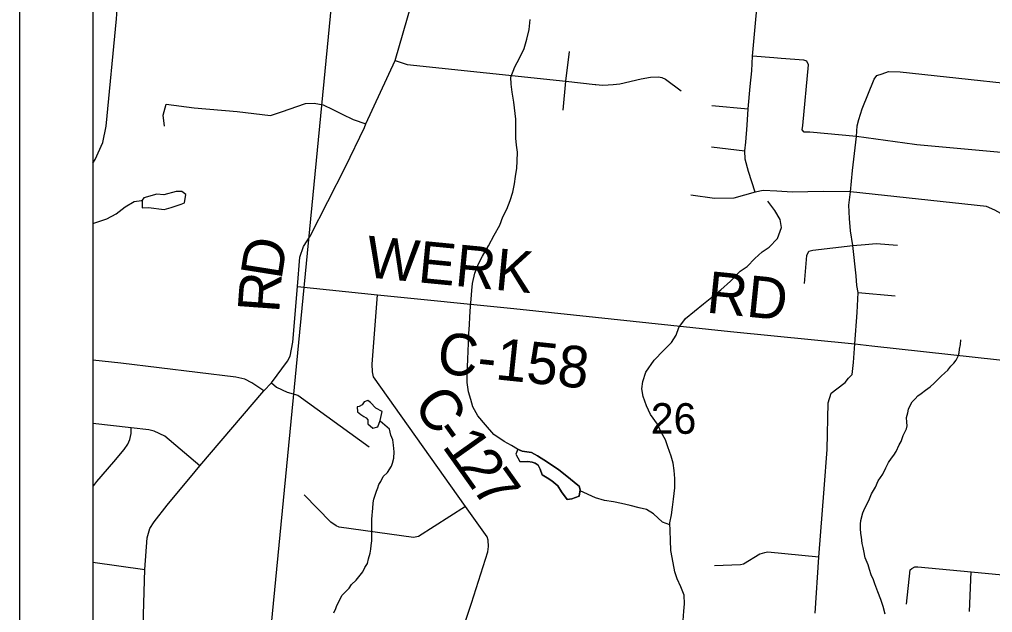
# Model space of a CAD drawing. Extents: x 0 to 34, y -2 to 22.
# Drawn here: x 2 to 3.329, y 19.146 to 19.956 of the extents above; entities that cross this region are included whole.
import ezdxf

# ---------------------------------------------------------------- set-up
doc = ezdxf.new("R2010")
doc.units = 0
for name, color, linetype in [('Default', 7, 'Continuous'), ('GM_X_County_Road', 7, 'Continuous'), ('GM_X_County_Road_Text', 7, 'Continuous'), ('GM_X_Minor_Lake', 7, 'Continuous'), ('GM_X_Minor_River', 7, 'Continuous'), ('GM_X_Rail_Line', 7, 'Continuous'), ('GM_X_Section', 7, 'Continuous'), ('GM_X_Section_Text', 7, 'Continuous'), ('GM_X_Township_Road', 7, 'Continuous'), ('SH_Cut_Line', 7, 'Continuous'), ('SH_Data', 7, 'Continuous')]:
    doc.layers.add(name, color=color, linetype=linetype)

msp = doc.modelspace()

# ---------------------------------------------------------------- linework, layer by layer
at = {"layer": 'Default'}
msp.add_lwpolyline([(2.1, 20.1369), (2.1, 19.1108), (2.3398, 19.083), (2.4387, 20.1012)], close=True, dxfattribs=at)
at = {"layer": 'GM_X_County_Road'}
msp.add_line((2.1, 19.2142), (2.1712, 19.2042), dxfattribs=at)
for points in [[(2.3338, 19.4483), (2.3443, 19.4595), (2.3661, 19.4889), (2.3697, 19.4957), (2.3732, 19.515), (2.3798, 19.5908), (2.3832, 19.631), (2.3882, 19.6456), (2.3969, 19.6595), (2.4454, 19.7543), (2.4712, 19.808), (2.4732, 19.813), (2.5131, 19.8995), (2.5409, 19.9962), (2.5554, 20.0405), (2.5666, 20.106), (2.5737, 20.177), (2.5781, 20.1967)], [(2.3798, 19.5908), (2.4889, 19.5795), (2.6752, 19.5607), (2.9711, 19.5296), (3.1409, 19.5124), (3.1645, 19.51), (3.4093, 19.4828)], [(2.5867, 19.0654), (2.6175, 19.1582), (2.6397, 19.2287), (2.6406, 19.2359), (2.6402, 19.2445), (2.6387, 19.2488), (2.6092, 19.2902), (2.4834, 19.4674), (2.4821, 19.4742), (2.4817, 19.4849), (2.4889, 19.5795)], [(2.2401, 19.3382), (2.2464, 19.3458), (2.3338, 19.4483)], [(2.1712, 19.2042), (2.1743, 19.2478), (2.178, 19.2602), (2.184, 19.2696), (2.2017, 19.2923), (2.2401, 19.3382)], [(2.1, 19.0714), (2.1174, 19.092), (2.1244, 19.0986), (2.1286, 19.1004), (2.1496, 19.1047), (2.1589, 19.1093), (2.1604, 19.11), (2.1668, 19.1189), (2.1689, 19.1276), (2.1712, 19.2042)]]:
    msp.add_lwpolyline(points, dxfattribs=at)
at = {"layer": 'GM_X_Minor_Lake'}
for points in [[(2.1977, 19.6963), (2.2072, 19.6987), (2.221, 19.7033), (2.2256, 19.7054), (2.2271, 19.7168), (2.2219, 19.7207), (2.2139, 19.7209), (2.1974, 19.7161), (2.1876, 19.7171), (2.17, 19.7122), (2.1676, 19.7087)], [(2.1676, 19.7087), (2.1677, 19.6982), (2.1761, 19.6988), (2.1977, 19.6963)], [(2.4926, 19.408), (2.4955, 19.4201), (2.4869, 19.4249), (2.4794, 19.4323), (2.4757, 19.4351), (2.4707, 19.4333), (2.468, 19.4292), (2.4641, 19.427), (2.4611, 19.4267), (2.4616, 19.4198), (2.4665, 19.4163), (2.4702, 19.4132), (2.4736, 19.4115), (2.4758, 19.4088)], [(2.4758, 19.4088), (2.476, 19.4031), (2.4827, 19.3976), (2.4896, 19.3993), (2.4926, 19.408)], [(2.6807, 19.3689), (2.6782, 19.3617), (2.6836, 19.352), (2.6943, 19.3521)], [(2.6805, 19.3689), (2.6867, 19.366), (2.6992, 19.3642), (2.7074, 19.3594), (2.7212, 19.351), (2.7369, 19.3403), (2.7499, 19.3301), (2.7604, 19.3215), (2.7644, 19.318), (2.7658, 19.313), (2.7645, 19.3046), (2.7545, 19.3011), (2.748, 19.3001), (2.7403, 19.3106), (2.7352, 19.3187), (2.727, 19.3254), (2.7207, 19.3294), (2.7139, 19.3337), (2.7111, 19.3414), (2.7086, 19.3468), (2.7045, 19.3496), (2.7003, 19.3508), (2.6943, 19.3521)], [(2.6943, 19.3521), (2.7003, 19.3508), (2.7045, 19.3496), (2.7086, 19.3468), (2.7111, 19.3414), (2.7139, 19.3337), (2.7207, 19.3294), (2.727, 19.3254), (2.7352, 19.3187), (2.7403, 19.3106), (2.748, 19.3001), (2.7545, 19.3011), (2.7645, 19.3046), (2.7658, 19.313), (2.7644, 19.318), (2.7604, 19.3215), (2.7499, 19.3301), (2.7369, 19.3403), (2.7212, 19.351), (2.7074, 19.3594), (2.6992, 19.3642), (2.6867, 19.366), (2.6807, 19.3689)]]:
    msp.add_lwpolyline(points, dxfattribs=at)
at = {"layer": 'GM_X_Minor_River'}
for points in [[(2.6805, 19.3689), (2.6722, 19.3736), (2.6621, 19.3792), (2.6479, 19.3887), (2.6365, 19.4019), (2.6263, 19.4144), (2.6194, 19.4264), (2.6166, 19.4364), (2.6135, 19.4471), (2.6116, 19.4597), (2.6115, 19.4703), (2.6122, 19.4813), (2.6125, 19.4916), (2.6129, 19.5026), (2.6132, 19.5136), (2.6139, 19.5269), (2.6147, 19.5387), (2.6154, 19.5497), (2.6161, 19.5634), (2.6168, 19.5736), (2.6179, 19.5854), (2.619, 19.5952), (2.622, 19.6092), (2.6269, 19.622), (2.6326, 19.6325), (2.6409, 19.6463), (2.6486, 19.6609), (2.6562, 19.6747), (2.6603, 19.686), (2.6656, 19.6965), (2.6701, 19.7082), (2.6738, 19.7199), (2.6761, 19.7312), (2.6775, 19.7414), (2.6793, 19.7524), (2.68, 19.7623), (2.6803, 19.7744), (2.6791, 19.784), (2.6782, 19.7935), (2.6782, 19.8068), (2.6782, 19.8197), (2.6751, 19.8426), (2.6732, 19.8564), (2.6716, 19.8671), (2.6712, 19.877), (2.6765, 19.8909), (2.6829, 19.9029), (2.6894, 19.916), (2.6932, 19.9288), (2.6962, 19.942), (2.6977, 19.9557)], [(2.1, 19.6768), (2.1194, 19.6832), (2.1321, 19.6901), (2.1446, 19.6996), (2.1569, 19.7069), (2.1665, 19.7085), (2.1676, 19.7087)], [(2.9064, 19.1346), (2.9076, 19.1475), (2.9086, 19.1573), (2.9078, 19.1691), (2.9036, 19.1806), (2.8986, 19.1914), (2.8954, 19.201), (2.8915, 19.2209), (2.8898, 19.2305), (2.8891, 19.2442), (2.8887, 19.2571), (2.8883, 19.2681), (2.8905, 19.2791), (2.8919, 19.2893), (2.8934, 19.3003), (2.895, 19.3159), (2.895, 19.3288), (2.8945, 19.3394), (2.8929, 19.3494), (2.8901, 19.359), (2.8856, 19.372), (2.8824, 19.3816), (2.8767, 19.392), (2.8713, 19.4028), (2.8618, 19.416), (2.8564, 19.428), (2.8519, 19.4407), (2.8503, 19.451), (2.8513, 19.4612), (2.8555, 19.474), (2.867, 19.4904), (2.8799, 19.5034), (2.8908, 19.5144), (2.8968, 19.5245), (2.9005, 19.5347), (2.91, 19.5474), (2.9221, 19.5573), (2.9345, 19.5672), (2.9458, 19.5764), (2.9582, 19.5863), (2.9711, 19.5981), (2.9844, 19.6118), (2.9941, 19.6183), (3.0047, 19.6291), (3.0144, 19.6383), (3.0241, 19.6448), (3.0355, 19.6567), (3.0408, 19.6714), (3.0393, 19.6824), (3.032, 19.6948), (3.0221, 19.7076)], [(3.1592, 19.2107), (3.1554, 19.2203), (3.1534, 19.2299), (3.1525, 19.2345), (3.1511, 19.2399), (3.1503, 19.2486), (3.1493, 19.2536), (3.1488, 19.2605), (3.1486, 19.2662), (3.1492, 19.2711), (3.1522, 19.2816), (3.1547, 19.288), (3.16, 19.2988), (3.1637, 19.3078), (3.1694, 19.3168), (3.1731, 19.3254), (3.1795, 19.3347), (3.1832, 19.3433), (3.1872, 19.3504), (3.1912, 19.3563), (3.1944, 19.3607), (3.1976, 19.3656), (3.2017, 19.3746), (3.2045, 19.379), (3.2071, 19.3873), (3.2095, 19.3918), (3.2116, 19.3966), (3.2125, 19.4008), (3.2119, 19.4058), (3.2117, 19.4118), (3.2135, 19.4182), (3.2144, 19.4235), (3.2165, 19.4284), (3.2193, 19.4332), (3.2236, 19.4373), (3.2272, 19.4417), (3.2319, 19.4446), (3.2377, 19.4493), (3.2439, 19.4537), (3.2494, 19.4588), (3.2545, 19.464), (3.2589, 19.4684), (3.264, 19.4728), (3.2679, 19.4768), (3.2723, 19.482), (3.2762, 19.486), (3.2794, 19.4905), (3.2822, 19.4957), (3.2835, 19.5002), (3.2841, 19.5055), (3.2854, 19.5119), (3.286, 19.518)], [(2.4691, 19.2011), (2.4719, 19.2071), (2.4752, 19.2127), (2.4769, 19.2187), (2.479, 19.2266), (2.48, 19.2319), (2.4806, 19.2372), (2.4812, 19.2437), (2.4813, 19.249), (2.4811, 19.2536), (2.4814, 19.2611), (2.4812, 19.268), (2.4814, 19.2733), (2.482, 19.2782), (2.4822, 19.2835), (2.4827, 19.2877), (2.4833, 19.2953), (2.4842, 19.3002), (2.4877, 19.3115), (2.4897, 19.316), (2.491, 19.3205), (2.4934, 19.3246), (2.4967, 19.3313), (2.5026, 19.3368), (2.5082, 19.3454), (2.5095, 19.3495), (2.5112, 19.3563), (2.5119, 19.365), (2.5111, 19.3741), (2.5102, 19.3814), (2.5074, 19.388), (2.5054, 19.396), (2.4929, 19.4071), (2.4926, 19.408)], [(2.8884, 19.2655), (2.8784, 19.2688), (2.8662, 19.2806), (2.8565, 19.2862), (2.8463, 19.2887), (2.8343, 19.2917), (2.8222, 19.2944), (2.8116, 19.2966), (2.7991, 19.2988), (2.7867, 19.3022), (2.7657, 19.312)], [(3.1827, 19.1434), (3.1797, 19.1537), (3.1783, 19.1579), (3.1766, 19.1633), (3.1724, 19.1737), (3.1686, 19.1849), (3.1665, 19.1903), (3.1633, 19.1972), (3.1613, 19.2045), (3.1592, 19.2107)], [(2.4292, 19.1451), (2.432, 19.1511), (2.4333, 19.1552), (2.441, 19.1694), (2.4504, 19.179), (2.4537, 19.1838), (2.4599, 19.19), (2.4635, 19.1945), (2.4691, 19.2011)]]:
    msp.add_lwpolyline(points, dxfattribs=at)
at = {"layer": 'GM_X_Rail_Line'}
msp.add_lwpolyline([(7.5809, 20.9), (2.1, 20.9), (2.1, 18.1368), (2.3446, 18.1102), (2.9298, 18.0171), (3.2869, 17.9604), (3.6832, 17.9108)], dxfattribs=at)
at = {"layer": 'GM_X_Section'}
msp.add_lwpolyline([(3.4541, 19.9967), (3.3818, 18.9832), (2.3398, 19.083), (2.4387, 20.1012)], close=True, dxfattribs=at)
at = {"layer": 'GM_X_Township_Road'}
for p, q in [((3.0306, 19.9031), (3.0015, 19.9057)), ((2.9459, 19.8381), (2.9953, 19.8335)), ((2.9453, 19.7817), (2.9906, 19.7763)), ((3.1454, 19.5828), (3.196, 19.5782)), ((3.2975, 19.1472), (3.3001, 19.201))]:
    msp.add_line(p, q, dxfattribs=at)
for points in [[(2.1, 19.7592), (2.1033, 19.7645), (2.114, 19.7875), (2.1183, 19.8101), (2.1325, 19.9567), (2.1345, 19.982), (2.1433, 20.0729)], [(2.9982, 19.8642), (3.0002, 19.8856), (3.0015, 19.9057), (3.0062, 19.9605), (3.0101, 19.9946), (3.0092, 20.0115), (3.008, 20.0229), (3.0037, 20.0394)], [(2.7427, 19.8318), (2.7462, 19.8716), (2.7512, 19.9119)], [(2.5131, 19.8995), (2.5298, 19.894), (2.7462, 19.8716), (2.7865, 19.8669), (2.7875, 19.8668)], [(3.2226, 19.785), (3.1435, 19.7956), (3.0796, 19.8017), (3.0719, 19.8017), (3.0693, 19.8049), (3.0702, 19.8107), (3.0776, 19.8935), (3.0756, 19.8985), (3.0716, 19.9002), (3.0403, 19.9022), (3.0306, 19.9031)], [(3.1435, 19.7956), (3.1444, 19.8106), (3.1465, 19.819), (3.1513, 19.8337), (3.1673, 19.8742), (3.1713, 19.879), (3.1782, 19.8815), (3.187, 19.8846), (3.2029, 19.8841), (3.4391, 19.8586)], [(2.7875, 19.8668), (2.7962, 19.8659), (2.8042, 19.8662), (2.8109, 19.8667), (2.8199, 19.8679), (2.8492, 19.8744), (2.8621, 19.8767), (2.8728, 19.8775), (2.8774, 19.8764), (2.8826, 19.8742), (2.9038, 19.8581)], [(3.005, 19.7196), (2.9957, 19.7478), (2.9915, 19.7649), (2.9906, 19.7763), (2.9921, 19.7883), (2.9942, 19.8115), (2.9953, 19.8335), (2.9982, 19.8642)], [(2.198, 19.8099), (2.1965, 19.825), (2.2002, 19.84), (2.2385, 19.8349), (2.2973, 19.8299), (2.3429, 19.8245), (2.3579, 19.8295), (2.3908, 19.8409), (2.4026, 19.8413), (2.4149, 19.839), (2.4281, 19.8327), (2.4406, 19.8261), (2.4559, 19.819), (2.4732, 19.813)], [(3.0868, 19.1448), (3.092, 19.221), (3.0993, 19.3146), (3.1031, 19.3681), (3.1048, 19.4322), (3.1086, 19.445), (3.1164, 19.4512), (3.128, 19.4596), (3.1324, 19.4659), (3.1376, 19.4708), (3.1391, 19.4873), (3.1409, 19.5124), (3.1442, 19.5552), (3.1454, 19.5828), (3.1439, 19.5924), (3.1427, 19.6053), (3.1382, 19.6468), (3.1353, 19.6669), (3.1338, 19.6839), (3.1329, 19.7019), (3.135, 19.7202), (3.138, 19.7496), (3.1435, 19.7956)], [(3.4345, 19.795), (3.4186, 19.7959), (3.4105, 19.7953), (3.4024, 19.792), (3.3924, 19.7847), (3.3807, 19.7753), (3.3706, 19.7724), (3.3612, 19.7723), (3.2256, 19.7846), (3.2226, 19.785)], [(3.0347, 19.721), (3.0158, 19.722), (3.005, 19.7196), (2.9756, 19.7115), (2.9495, 19.7112), (2.9172, 19.7155)], [(3.4238, 19.6478), (3.3826, 19.6512), (3.3762, 19.6529), (3.3445, 19.6885), (3.3325, 19.6954), (3.3211, 19.7002), (3.135, 19.7202), (3.0982, 19.7207), (3.0555, 19.7199), (3.0347, 19.721)], [(3.0723, 19.5951), (3.0757, 19.6333), (3.0783, 19.6393), (3.0836, 19.6406), (3.1382, 19.6468), (3.1553, 19.6483), (3.1702, 19.6498), (3.1993, 19.6472)], [(2.3338, 19.4483), (2.3172, 19.4594), (2.3077, 19.4644), (2.2956, 19.4671), (2.1385, 19.4861), (2.1, 19.4905)], [(2.3443, 19.4595), (2.3512, 19.4534), (2.3658, 19.4467), (2.3801, 19.4426), (2.4776, 19.3718)], [(2.2464, 19.3458), (2.1987, 19.3866), (2.1842, 19.3934), (2.1766, 19.3953), (2.1524, 19.3978), (2.1, 19.4038)], [(2.1, 19.3178), (2.1017, 19.3192), (2.1058, 19.3245), (2.1289, 19.3516), (2.143, 19.3682), (2.1481, 19.3757), (2.1506, 19.3818), (2.1525, 19.3902), (2.1524, 19.3978)], [(2.6092, 19.2902), (2.5449, 19.2496), (2.5384, 19.2479), (2.4368, 19.2622), (2.4327, 19.2639), (2.4253, 19.269), (2.389, 19.3063)], [(3.092, 19.221), (3.0222, 19.2278), (3.0177, 19.2272), (3.0115, 19.2251), (2.9891, 19.2118), (2.9849, 19.2108), (2.9492, 19.2093)], [(3.2117, 19.1568), (3.2167, 19.2041), (3.219, 19.2059), (3.2229, 19.2081), (3.226, 19.208), (3.2271, 19.2079), (3.3001, 19.201), (3.3907, 19.1924)]]:
    msp.add_lwpolyline(points, dxfattribs=at)
at = {"layer": 'SH_Cut_Line'}
msp.add_lwpolyline([(8.9, 20.9), (2.1, 20.9), (2.1, 16.3648), (2.1342, 16.3571), (2.2291, 16.3515), (2.5217, 16.3621), (2.6166, 16.3275), (2.9069, 16.2111), (3.202, 16.0321), (3.297, 15.9555), (3.6339, 15.5717)], dxfattribs=at)
at = {"layer": 'SH_Data'}
for p, q in [((2, 21), (2, 14)), ((2.1, 20.9), (2.1, 14.1))]:
    msp.add_line(p, q, dxfattribs=at)

# ---------------------------------------------------------------- texts
at = {"layer": 'GM_X_County_Road_Text'}
for s, height, rotation, p in [('WERK', 0.05682, 354.4546, (2.4717, 19.6038)), ('D', 0.0568, 80.9539, (2.3578, 19.5991)), ('R', 0.0568, 85.8454, (2.3546, 19.5539)), ('RD', 0.05682, 354.1938, (2.9371, 19.5555)), ('C-158', 0.05682, 353.9906, (2.5691, 19.4727)), ('C', 0.0568, 305.3822, (2.5362, 19.4293)), ('1', 0.0568, 305.3825, (2.5764, 19.3727)), ('-', 0.0568, 305.3823, (2.563, 19.3915)), ('2', 0.0568, 305.3916, (2.5965, 19.3444)), ('7', 0.0568, 305.441, (2.6167, 19.316))]:
    msp.add_text(s, height=height, rotation=rotation, dxfattribs=at).set_placement(p)
at = {"layer": 'GM_X_Section_Text'}
msp.add_text('26', height=0.04186, rotation=0, dxfattribs=at).set_placement((2.8623, 19.3897))

doc.saveas('drawing.dxf')
